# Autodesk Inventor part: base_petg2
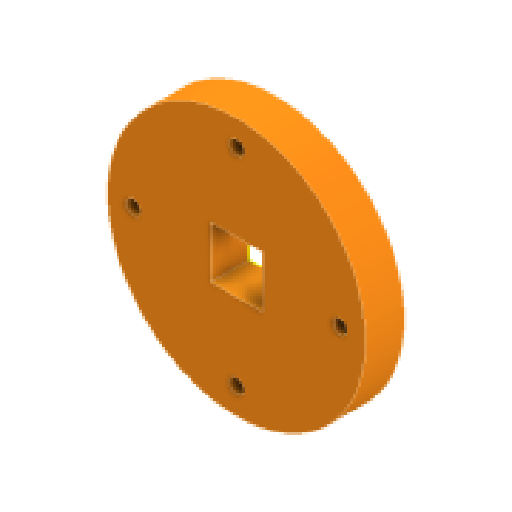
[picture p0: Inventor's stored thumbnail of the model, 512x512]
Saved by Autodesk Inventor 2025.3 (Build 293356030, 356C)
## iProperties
Created: 2025-09
Part Number: base_petg2
Material: Plastica PET
Document SubType Name: Modeling
Designer: Ryzen5700u
Density: 1.541 g/cm^3
Appearance: Arancione
Author: Ryzen5700u
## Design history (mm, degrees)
sketch "Schizzo1"
  geometry: C1 r 50 at (0, 0); 1 further point
  constraints: 1 centre point, 1 coincident
  dimensions: "d0" = 100 diameter of C1
extrude "Estrusione1" new body sketch "Schizzo1" distance "d1" = 15; taper "d2" = 0 deg
sketch "Schizzo2"
  geometry: 2 further points
  dimensions: "d3" = 40 distance of point (0, 0) point (0, 40)
hole "Foro1" sketch "Schizzo2" at (0, 40) diameter "d4" = 5.5; stored, may be unused: countersink angle "d8" = 90 deg, drill point angle "d10" = 118 deg; dims "d5" = 6, "d6" = 9, "d7" = 4, "d9" = 8
pattern_circular "Serie circolare1" dims angle "d12" = 360 deg
sketch "Schizzo5"
  geometry: L1 (10.05, 10.05)-(-10.05, 10.05); L2 (-10.05, 10.05)-(-10.05, -10.05); L3 (-10.05, -10.05)-(10.05, -10.05); L4 (10.05, -10.05)-(10.05, 10.05); L5 (10.05, 10.05)-(-10.05, -10.05); L6 (-10.05, 10.05)-(10.05, -10.05); 1 further point
  constraints: 12 end point, 2 midpoint, 2 parallel, 1 horizontal, 1 perpendicular
  dimensions: "d27" = 20.1 distance of L3.end L2.end; "d28" = 20.1 distance of L2.end L1.end
extrude "Estrusione3" cut sketch "Schizzo5" extent not by distance; stored distance "d29" = 0; taper "d30" = 0 deg
sketch "Schizzo8"
  geometry: L1 (10.05, -10.05)-(-10.05, -10.05) reference; L2 (-10.05, -10.05)-(-10.05, 10.05) reference; L3 (-10.05, 10.05)-(10.05, 10.05) reference; L4 (10.05, 10.05)-(10.05, -10.05) reference; L5 (18.05, -18.05)-(-18.05, -18.05); L6 (-18.05, -18.05)-(-18.05, 18.05); L7 (-18.05, 18.05)-(18.05, 18.05); L8 (18.05, 18.05)-(18.05, -18.05); C1 r 4.5 at (-40, 0) reference; C2 r 4.5 at (0, -40) reference; C3 r 4.5 at (40, 0) reference; C4 r 4.5 at (0, 40) reference; C5 r 50 at (0, 0) reference; 1 further point
  constraints: 8 end point, 3 other
  dimensions: "d35" = 8 distance between parallel lines of L4 L8
extrude "Estrusione5" join sketch "Schizzo8" distance "d36" = 30; taper "d37" = 0 deg
fillet "Raccordo1" dims "d38" = 5
fillet "Raccordo2" dims "d39" = 2
sketch "Schizzo9"
  geometry: L1 (26.1, -23)-(0, -23) reference; L2 (26.1, 0)-(26.1, -23) reference; L3 (0, 0)-(26.1, 0) reference; L4 (0, -23)-(0, 0) reference; L5 (-5, 0)-(0, 0) reference; L6 (26.1, -23)-(0, 0); L7 (0, 0)-(0, -23); L8 (26.1, 0)-(31.1, 0) reference; L9 (26.1, 0)-(0, -23); 2 further points
  constraints: 6 end point, 1 collinear, 1 midpoint
hole "Foro3" sketch "Schizzo9" at (13.05, -11.5) diameter "d40" = 4.5; stored, may be unused: countersink angle "d44" = 90 deg, drill point angle "d46" = 118 deg; dims "d41" = 6, "d42" = 8, "d43" = 4.6, "d45" = 8
sketch "Schizzo10"
  geometry: C1 r 2.25 at (13.05, -11.5) reference; 2 further points
  constraints: 1 coincident
hole "Foro4" sketch "Schizzo10" at (13.05, -11.5) diameter "d48" = 4.5; stored, may be unused: countersink angle "d52" = 90 deg, drill point angle "d54" = 118 deg; dims "d49" = 6, "d50" = 8, "d51" = 3, "d53" = 8
fillet "Raccordo3" dims "d47" = 2
pattern_circular "Serie circolare2" dims "d63" = 360 deg
node "Solido1"
node "Linea chiusa proiettata1"
node "Linea chiusa proiettata2"
